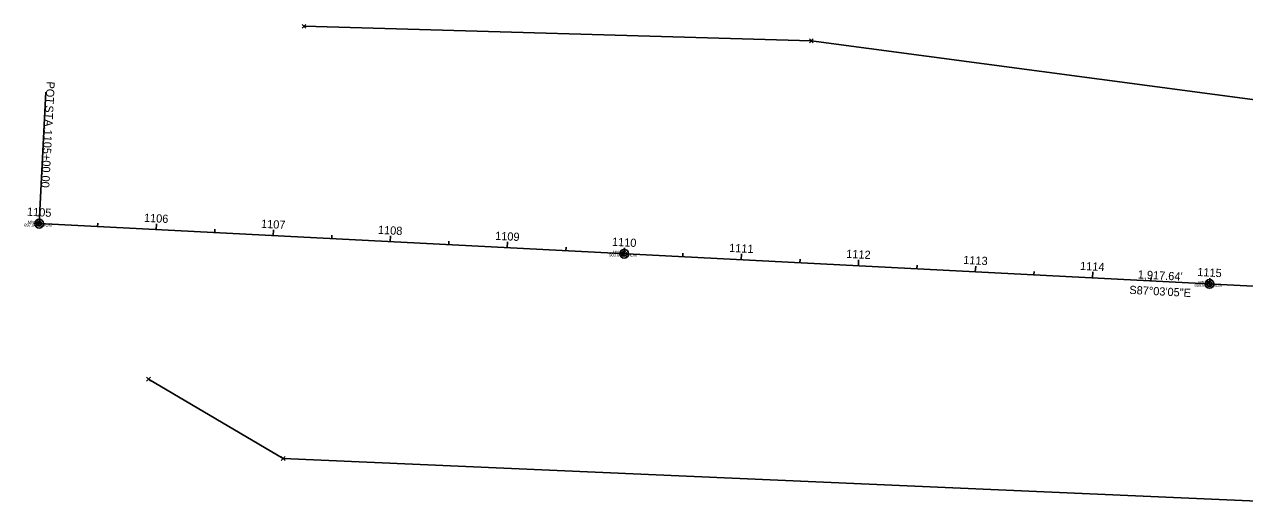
# Model space of a CAD drawing. Extents: x 2082101 to 2090447, y 708207 to 709766.
# Drawn here: x 2082101 to 2083142, y 708332 to 708745 of the extents above; entities that cross this region are included whole.
import ezdxf

# ---------------------------------------------------------------- set-up
doc = ezdxf.new("R2010")
doc.units = 0
for name, color, linetype in [('DR_X_Ditch', 7, 'Continuous'), ('DR_X_Elev_Flow', 7, 'Continuous'), ('GK_Drainage_Nodes', 7, 'Continuous'), ('SN_X_Public', 7, 'Continuous'), ('SV_X_Break_Lines', 7, 'Continuous'), ('SV_X_Mon_Cells_Found', 7, 'Continuous'), ('SV_X_Shot_Marker', 7, 'Continuous'), ('SV_X_Text_Comment', 7, 'Continuous'), ('SV_X_Text_Elevation', 7, 'Continuous'), ('SV_X_Text_Name', 7, 'Continuous'), ('SV_X_Toe_of_Slope', 7, 'Continuous'), ('VG_X_Cells', 7, 'Continuous')]:
    doc.layers.add(name, color=color, linetype=linetype)

msp = doc.modelspace()

# ---------------------------------------------------------------- linework, layer by layer
at = {"layer": 'DR_X_Ditch'}
for p, q in [((2082339.4, 708743.2), (2082772.2, 708730.9)), ((2082339.4, 708743.2), (2082772.2, 708730.9)), ((2082772.2, 708730.9), (2083319.2, 708657.7)), ((2082772.2, 708730.9), (2083319.2, 708657.7)), ((2082206.6, 708441.6), (2082321.6, 708374)), ((2082321.6, 708374), (2083277.4, 708332))]:
    msp.add_line(p, q, dxfattribs=at)
at = {"layer": 'DR_X_Elev_Flow'}
msp.add_line((2082113.3, 708574.6), (2082119.1, 708686.9), dxfattribs=at)
msp.add_circle((2082113.3, 708574.6), 1.5, dxfattribs=at)
at = {"layer": 'GK_Drainage_Nodes'}
for p, q in [((2082113.3, 708574.6), (2082113.6, 708579.6)), ((2082163.2, 708572), (2082163.4, 708575)), ((2082213.2, 708569.4), (2082213.4, 708574.4)), ((2082263.1, 708566.9), (2082263.3, 708569.8)), ((2082313, 708564.3), (2082313.3, 708569.3)), ((2082363, 708561.7), (2082363.1, 708564.7)), ((2082412.9, 708559.1), (2082413.2, 708564.1)), ((2082462.8, 708556.6), (2082463, 708559.6)), ((2082512.8, 708554), (2082513, 708559)), ((2082562.7, 708551.4), (2082562.9, 708554.4)), ((2082612.6, 708548.9), (2082612.9, 708553.8)), ((2082662.6, 708546.3), (2082662.7, 708549.3)), ((2082712.5, 708543.7), (2082712.8, 708548.7)), ((2082762.4, 708541.1), (2082762.6, 708544.1)), ((2082812.4, 708538.6), (2082812.6, 708543.6)), ((2082862.3, 708536), (2082862.5, 708539)), ((2082912.2, 708533.4), (2082912.5, 708538.4)), ((2082962.2, 708530.8), (2082962.3, 708533.8)), ((2083012.1, 708528.3), (2083012.4, 708533.3)), ((2083062, 708525.7), (2083062.2, 708528.7)), ((2083112, 708523.1), (2083112.2, 708528.1))]:
    msp.add_line(p, q, dxfattribs=at)
at = {"layer": 'SV_X_Break_Lines'}
for p, q in [((2082337.7, 708741.5), (2082341, 708744.8)), ((2082337.7, 708744.8), (2082341, 708741.5)), ((2082770.6, 708729.2), (2082773.9, 708732.6)), ((2082770.6, 708732.6), (2082773.9, 708729.2)), ((2082204.9, 708439.9), (2082208.3, 708443.3)), ((2082204.9, 708443.3), (2082208.3, 708439.9)), ((2082319.9, 708372.3), (2082323.2, 708375.7)), ((2082319.9, 708375.7), (2082323.2, 708372.3))]:
    msp.add_line(p, q, dxfattribs=at)
at = {"layer": 'SV_X_Shot_Marker'}
msp.add_line((2082113.3, 708574.6), (2084028.4, 708475.9), dxfattribs=at)
at = {"layer": 'SV_X_Text_Name'}
for p, q in [((2082110.3, 708572.3), (2082113.8, 708575.4)), ((2082110.5, 708575.6), (2082113.7, 708572.1)), ((2082609.8, 708547.1), (2082613.1, 708550.5)), ((2082609.8, 708550.5), (2082613.1, 708547.1)), ((2083109.2, 708522.1), (2083112.5, 708525.4)), ((2083109.2, 708525.4), (2083112.5, 708522.1))]:
    msp.add_line(p, q, dxfattribs=at)
at = {"layer": 'SV_X_Toe_of_Slope'}
for centre, radius in [((2082113.3, 708574.6), 3.75), ((2082113.3, 708574.6), 2), ((2082612.6, 708548.9), 3.75), ((2082612.6, 708548.9), 2), ((2083112, 708523.1), 3.75), ((2083112, 708523.1), 2)]:
    msp.add_circle(centre, radius, dxfattribs=at)

# ---------------------------------------------------------------- texts
at = {"layer": 'DR_X_Elev_Flow'}
for s, p in [('POT', (2082119.7, 708696.2)), (' STA. ', (2082118.7, 708678.4)), ('1105+00.00', (2082117.5, 708655.1))]:
    msp.add_text(s, height=7, rotation=267.0515, dxfattribs=at).set_placement(p)
at = {"layer": 'GK_Drainage_Nodes'}
for s, p in [('1105', (2082102.8, 708581.4)), ('1106', (2082202.6, 708576.2)), ('1107', (2082302.5, 708571.1)), ('1108', (2082402.3, 708565.9)), ('1109', (2082502.3, 708560.8)), ('1110', (2082602, 708555.7)), ('1111', (2082702, 708550.5)), ('1112', (2082801.9, 708545.4)), ('1113', (2082901.8, 708540.2)), ('1114', (2083001.5, 708535.1)), ('1115', (2083101.5, 708529.9))]:
    msp.add_text(s, height=7, rotation=357.0515, dxfattribs=at).set_placement(p)
at = {"layer": 'SN_X_Public'}
msp.add_text('S87°03\'05"E', height=7, rotation=357.0515, dxfattribs=at).set_placement((2083043.5, 708514.6))
at = {"layer": 'SV_X_Mon_Cells_Found'}
for p in [(2082113.3, 708572.1), (2082612.6, 708546.4), (2083112, 708520.6)]:
    msp.add_text('CMON', height=2.5, dxfattribs=at).set_placement(p)
at = {"layer": 'SV_X_Text_Comment'}
for s, p in [('897.877', (2082100.6, 708572.1)), ('903.690', (2082599.8, 708546.4)), ('909.698', (2083099.2, 708520.6))]:
    msp.add_text(s, height=2.5, dxfattribs=at).set_placement(p)
at = {"layer": 'SV_X_Text_Elevation'}
for s, p in [('MN10', (2082103.6, 708574.6)), ('MN11', (2082603, 708548.9)), ('MN12', (2083102.4, 708523.1))]:
    msp.add_text(s, height=2.5, dxfattribs=at).set_placement(p)
at = {"layer": 'VG_X_Cells'}
msp.add_text("1,917.64'", height=7, rotation=357.0515, dxfattribs=at).set_placement((2083050.7, 708527.8))

doc.saveas('drawing.dxf')
